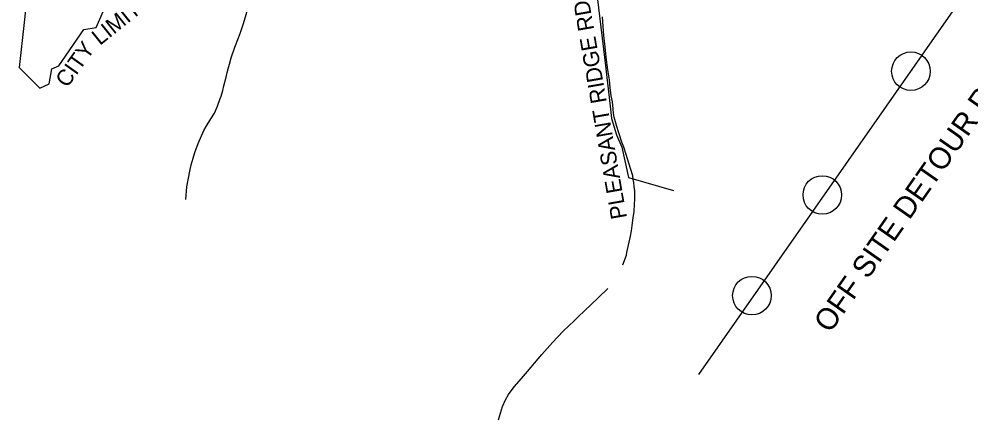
# Model space of a CAD drawing. Extents: x 1731327 to 1735374, y 884856 to 889832.
# Drawn here: x 1731411.6 to 1731719.5, y 885142.4 to 885272.1 of the extents above; entities that cross this region are included whole.
import ezdxf

# ---------------------------------------------------------------- set-up
doc = ezdxf.new("R2010")
doc.units = 0
for name, color, linetype in [('Exist Horizontal Baseline Alignment', 7, 'Continuous'), ('Exist Other Culture Located Object CELL', 7, 'Continuous'), ('Exist Other Culture Sign Text', 7, 'Continuous'), ('Exist Structure Major Deck Tunnel Box Culvert Text', 7, 'Continuous')]:
    doc.layers.add(name, color=color, linetype=linetype)

msp = doc.modelspace()

# ---------------------------------------------------------------- linework, layer by layer
at = {"layer": 'Exist Horizontal Baseline Alignment'}
msp.add_line((1731631.46, 885157.08), (1731748.15, 885324.05), dxfattribs=at)
for centre in [(1731700.06, 885255.24), (1731671.39, 885215.2), (1731648.63, 885182.63)]:
    msp.add_circle(centre, 6.24, dxfattribs=at)
at = {"layer": 'Exist Other Culture Located Object CELL'}
for points in [[(1731484.17, 885270.72), (1731485.07, 885273.54), (1731485.58, 885275.43), (1731486.06, 885277.15), (1731486.44, 885278.66), (1731487.03, 885280.74), (1731487.53, 885282.49), (1731488.01, 885283.93)], [(1731605.49, 885235.63), (1731604.93, 885237.33), (1731604.5, 885238.9), (1731604.12, 885240.33), (1731603.9, 885241.55), (1731603.77, 885243.05), (1731603.5, 885245.38), (1731603.14, 885247.23), (1731602.75, 885249.96), (1731602.51, 885252.4), (1731602, 885255.74), (1731601.51, 885259.79), (1731601.13, 885263.18), (1731600.77, 885266.81), (1731600.54, 885269.66), (1731600.3, 885272.86)], [(1731473.56, 885239.85), (1731474.76, 885241.63), (1731475.76, 885243.92), (1731476.65, 885246.39), (1731476.92, 885247.12), (1731477.45, 885249.05), (1731477.84, 885250.48), (1731478.59, 885253.35), (1731478.85, 885254.79), (1731479.17, 885256.01), (1731479.62, 885257.51), (1731480.18, 885259.52), (1731480.49, 885260.57), (1731480.91, 885261.7), (1731481.4, 885263.06), (1731482.53, 885266), (1731483.18, 885267.81), (1731483.78, 885269.38), (1731484.17, 885270.72)], [(1731465.46, 885213.72), (1731465.89, 885217.78), (1731466.82, 885222.89), (1731467.28, 885224.94), (1731467.87, 885227.06), (1731468.44, 885228.94), (1731469.5, 885231.87), (1731471.36, 885236.03), (1731472.04, 885237.32), (1731473.56, 885239.85)], [(1731610.06, 885221.41), (1731608.83, 885225.5), (1731607.99, 885228.24), (1731607.15, 885230.65), (1731606.59, 885232.29), (1731605.49, 885235.63)], [(1731608.16, 885196.56), (1731609.36, 885201.82), (1731609.63, 885203.6), (1731609.85, 885205.33), (1731610.24, 885207.8), (1731610.51, 885209.8), (1731610.69, 885212.18), (1731610.77, 885213.73), (1731610.78, 885215.4), (1731610.7, 885216.53), (1731610.56, 885217.93), (1731610.4, 885219.19), (1731610.18, 885220.21), (1731610.06, 885221.41)], [(1731606.85, 885192.55), (1731608.01, 885195.72), (1731608.16, 885196.56)], [(1731590.98, 885174.39), (1731592.53, 885175.85), (1731596.55, 885179.66), (1731599, 885182.04), (1731602.02, 885184.95)], [(1731580.69, 885163.61), (1731584.17, 885167.46), (1731587.57, 885171.1), (1731589.39, 885172.87), (1731590.98, 885174.39)], [(1731569.84, 885150.6), (1731571.69, 885153.12), (1731574.11, 885155.78), (1731576.01, 885158.08), (1731577.21, 885159.51), (1731578.26, 885160.77), (1731580.69, 885163.61)], [(1731567.99, 885146.8), (1731568.88, 885148.88), (1731569.84, 885150.6)], [(1731566.62, 885142.4), (1731567.99, 885146.8)]]:
    msp.add_lwpolyline(points, dxfattribs=at)
at = {"layer": 'Exist Other Culture Sign Text'}
for points in [[(1731621.21, 885285.63), (1731604.29, 885297.72), (1731597.71, 885286.54), (1731601.08, 885258.79), (1731602.72, 885243.98), (1731603.2, 885239.96), (1731604.85, 885234.71), (1731606.54, 885230.67), (1731608.72, 885220.89), (1731623.22, 885216.66)], [(1731415.28, 885289.63), (1731411.56, 885256.44), (1731418.33, 885249.72), (1731421.31, 885251.13), (1731422.21, 885255.99), (1731424.38, 885256.96), (1731432.57, 885268.69), (1731436.56, 885269.4), (1731438.83, 885274.8)]]:
    msp.add_lwpolyline(points, dxfattribs=at)

# ---------------------------------------------------------------- texts
at = {"layer": 'Exist Horizontal Baseline Alignment'}
msp.add_text('OFF SITE DETOUR ROUTE', height=7, rotation=55.0074, dxfattribs=at).set_placement((1731673.89, 885170.22))
at = {"layer": 'Exist Structure Major Deck Tunnel Box Culvert Text'}
for s, rotation, p in [('LIMIT', 38.7031, (1731437.7, 885263.41)), ('PLEASANT RIDGE RD', 99.912, (1731608.25, 885207.85)), ('CITY', 54.4154, (1731427.14, 885249.63))]:
    msp.add_text(s, height=5.163, rotation=rotation, dxfattribs=at).set_placement(p)

doc.saveas('drawing.dxf')
